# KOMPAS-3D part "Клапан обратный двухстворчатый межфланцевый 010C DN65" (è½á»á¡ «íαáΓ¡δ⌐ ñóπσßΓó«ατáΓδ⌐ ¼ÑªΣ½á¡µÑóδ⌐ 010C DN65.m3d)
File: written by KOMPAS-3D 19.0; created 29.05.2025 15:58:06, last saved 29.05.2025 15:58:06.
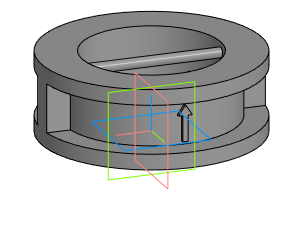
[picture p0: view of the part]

Document properties: Полное имя файла: E:\Dendor Работа Сачек\3D для проекитирвщиков\5.2 Тип 010C, 010C.Y Клапан обратный двухстворчатый межфланцевый\stp_Клапан обратный двухстворчатый межфланцевый 010C\Клапан обратный двухстворчатый межфланцевый 010C DN65.m3d

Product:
- Part/product: Клапан обратный двухстворчатый межфланцевый 010C DN65

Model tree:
1. Операция без истории:1  (labels: Клапан обратный двухстворчатый межфланцевый 010C DN65)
